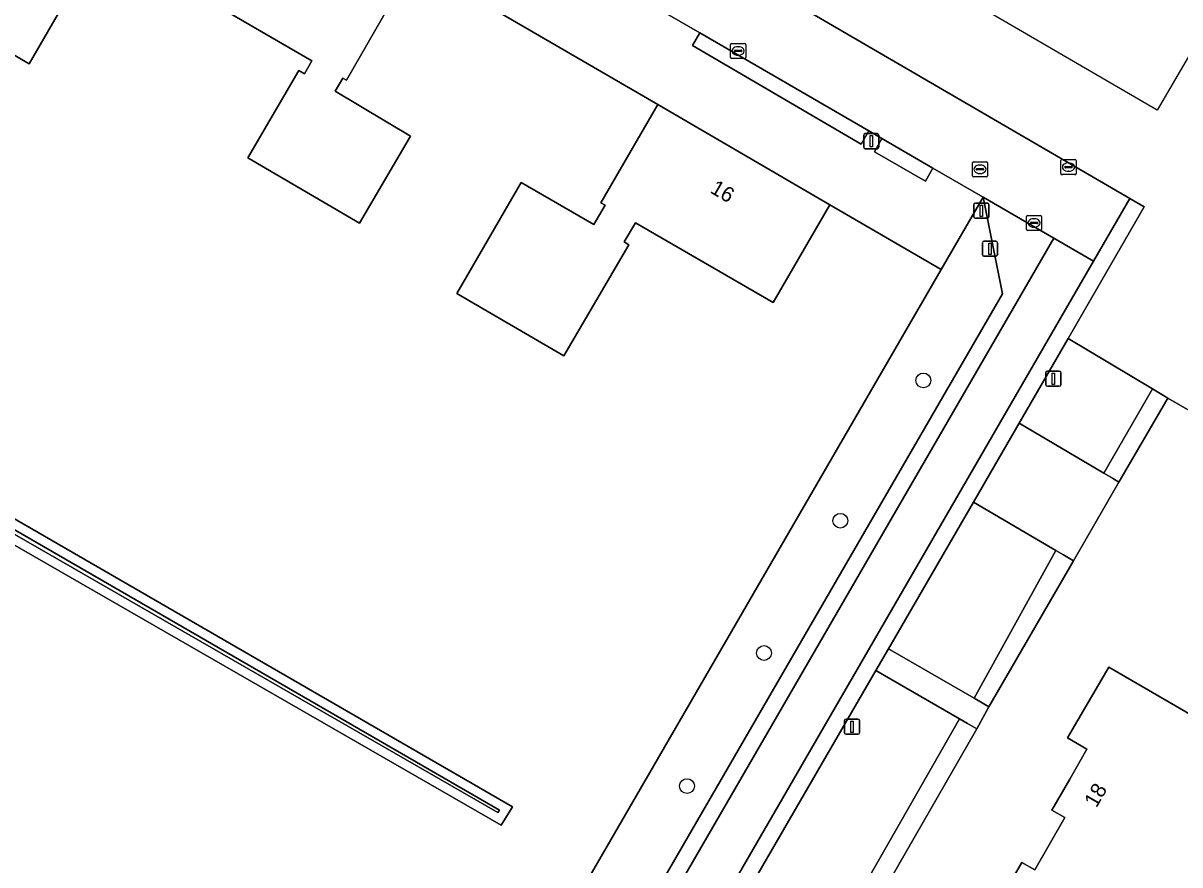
# Model space of a CAD drawing. Extents: x 156502 to 159075, y 384229 to 386100.
# Drawn here: x 157141.1 to 157217.5, y 385763.4 to 385818.9 of the extents above; entities that cross this region are included whole.
import ezdxf

# ---------------------------------------------------------------- set-up
doc = ezdxf.new("R2010")
doc.units = 0
for name, color, linetype in [('IMGEO_Afsluitpaal', 7, 'Continuous'), ('IMGEO_Berm_groen', 7, 'Continuous'), ('IMGEO_Boom', 7, 'Continuous'), ('IMGEO_Erf', 7, 'Continuous'), ('IMGEO_Grasland_overig', 7, 'Continuous'), ('IMGEO_Groenvoorziening', 7, 'Continuous'), ('IMGEO_Haag', 7, 'Continuous'), ('IMGEO_Hek', 7, 'Continuous'), ('IMGEO_Kolk', 7, 'Continuous'), ('IMGEO_Lichtmast', 7, 'Continuous'), ('IMGEO_Oever', 7, 'Continuous'), ('IMGEO_Pand', 7, 'Continuous'), ('IMGEO_Pand_nummerreeks', 7, 'Continuous'), ('IMGEO_Pand_vergunning_verleend', 7, 'Continuous'), ('IMGEO_Rijbaan_lokaal_gesloten', 7, 'Continuous'), ('IMGEO_Rijbaan_lokaal_halfverhard', 7, 'Continuous'), ('IMGEO_Rijbaan_lokaal_open', 7, 'Continuous'), ('IMGEO_Rioolput', 7, 'Continuous'), ('IMGEO_Voetpad_open', 7, 'Continuous'), ('IMGEO_Waterloop', 7, 'Continuous')]:
    doc.layers.add(name, color=color, linetype=linetype)

msp = doc.modelspace()

# ---------------------------------------------------------------- linework, layer by layer
at = {"layer": 'IMGEO_Afsluitpaal'}
for p, q in [((157203.9, 385806.17), (157203.9, 385806.97)), ((157203.9, 385806.97), (157203.9, 385806.17)), ((157204, 385807.07), (157204.79, 385807.07)), ((157204.79, 385807.07), (157204, 385807.07)), ((157204.89, 385806.97), (157204.89, 385806.17)), ((157204.89, 385806.17), (157204.89, 385806.97)), ((157204.79, 385806.07), (157204, 385806.07)), ((157204, 385806.07), (157204.79, 385806.07)), ((157204.466, 385803.659), (157204.466, 385804.459)), ((157204.466, 385804.459), (157204.466, 385803.659)), ((157204.566, 385804.559), (157205.356, 385804.559)), ((157205.356, 385804.559), (157204.566, 385804.559)), ((157205.456, 385804.459), (157205.456, 385803.659)), ((157205.456, 385803.659), (157205.456, 385804.459)), ((157205.356, 385803.559), (157204.566, 385803.559)), ((157204.566, 385803.559), (157205.356, 385803.559))]:
    msp.add_line(p, q, dxfattribs=at)
for points in [[(157204.32, 385806.945), (157204.47, 385806.945), (157204.47, 385806.195), (157204.32, 385806.195), (157204.32, 385806.945)], [(157204.886, 385804.434), (157205.036, 385804.434), (157205.036, 385803.684), (157204.886, 385803.684), (157204.886, 385804.434)]]:
    msp.add_lwpolyline(points, dxfattribs=at)
for centre, start, end in [((157204, 385806.97), 90, 180), ((157204, 385806.97), 90, 180), ((157204.79, 385806.97), 0, 90), ((157204.79, 385806.97), 360, 90), ((157204, 385806.17), 180, 270), ((157204, 385806.17), 180, 270), ((157204.79, 385806.17), 270, 0), ((157204.79, 385806.17), 270, 0), ((157204.566, 385804.459), 90, 180), ((157204.566, 385804.459), 90, 180), ((157205.356, 385804.459), 0, 90), ((157205.356, 385804.459), 360, 90), ((157204.566, 385803.659), 180, 270), ((157204.566, 385803.659), 180, 270), ((157205.356, 385803.659), 270, 0), ((157205.356, 385803.659), 270, 0)]:
    msp.add_arc(centre, 0.1, start, end, dxfattribs=at)
at = {"layer": 'IMGEO_Berm_groen'}
for points in [[(157205.798, 385801.093), (157204.517, 385807.457), (157201.732, 385802.693), (157157.489, 385726.3), (157149.855, 385730.69), (157148.433, 385728.196), (157156.009, 385723.887)], [(157162.191, 385725.838), (157205.798, 385801.093)]]:
    msp.add_lwpolyline(points, dxfattribs=at)
at = {"layer": 'IMGEO_Boom'}
for centre in [(157200.566, 385795.368), (157195.082, 385786.106), (157190.045, 385777.377), (157184.958, 385768.592)]:
    msp.add_circle(centre, 0.489, dxfattribs=at)
at = {"layer": 'IMGEO_Erf'}
for points in [[(157042.786, 385843.67), (157065.314, 385829.887), (157068.346, 385827.983), (157173.435, 385767.228), (157172.677, 385766.006), (157064.372, 385828.327), (157041.356, 385841.775)], [(157131.197, 385741.421), (157144.11, 385733.995), (157149.855, 385730.69), (157157.489, 385726.3), (157201.732, 385802.693), (157194.383, 385806.952), (157190.645, 385800.522), (157181.547, 385805.765), (157180.811, 385804.505), (157181.113, 385804.328), (157176.827, 385796.988), (157169.771, 385801.108), (157174.018, 385808.44), (157178.814, 385805.661), (157179.553, 385806.928), (157179.259, 385807.099), (157183.031, 385813.57), (157159.85, 385827.054)], [(157146.528, 385824.906), (157141.519, 385816.264), (157134.144, 385820.573)], [(157166.175, 385821.643), (157162.465, 385815.184), (157162.231, 385815.319), (157161.733, 385814.451), (157166.702, 385811.491), (157163.329, 385805.74), (157155.962, 385810.061), (157159.324, 385815.821), (157159.704, 385815.599), (157160.195, 385816.468), (157151.075, 385821.767)], [(157300.611, 385725.628), (157250.886, 385753.432), (157232.436, 385728.117), (157222.966, 385734.271), (157242.958, 385769.961), (157246.925, 385776.791), (157216.71, 385794.202), (157213.481, 385788.661), (157210.483, 385783.472), (157204.894, 385773.824), (157204.086, 385772.373), (157190.66, 385749.032), (157190.191, 385748.219), (157189.585, 385747.166), (157173.064, 385718.503), (157188.558, 385701.554)]]:
    msp.add_lwpolyline(points, dxfattribs=at)
msp.add_lwpolyline([(157216.825, 385762.498), (157214.836, 385759.028), (157215.782, 385758.513), (157212.125, 385752.188), (157207.442, 385754.89), (157208.164, 385756.155), (157204.143, 385758.489), (157207.06, 385763.557), (157207.934, 385763.062), (157209.905, 385766.51), (157209.04, 385767.011), (157210.228, 385769.058), (157211.364, 385771.036), (157210.092, 385771.773), (157212.805, 385776.435), (157227.391, 385767.994), (157224.692, 385763.333), (157223.414, 385764.038), (157221.09, 385760.054)], close=True, dxfattribs=at)
at = {"layer": 'IMGEO_Grasland_overig'}
msp.add_lwpolyline([(157186.511, 385823.495), (157214.196, 385807.371), (157215.153, 385806.818), (157210.12, 385798.131), (157215.692, 385794.809), (157216.71, 385794.202), (157246.925, 385776.791), (157272.043, 385820.045)], dxfattribs=at)
at = {"layer": 'IMGEO_Groenvoorziening'}
for points in [[(157196.965, 385811.84), (157185.809, 385818.305), (157185.313, 385817.465), (157196.454, 385810.969)], [(157197.832, 385811.333), (157197.341, 385810.462), (157200.709, 385808.513), (157201.192, 385809.384)], [(157215.606, 385794.649), (157215.692, 385794.809), (157210.12, 385798.131), (157206.888, 385792.553), (157212.477, 385789.254)], [(157216.71, 385794.202), (157215.692, 385794.809), (157215.606, 385794.649), (157212.477, 385789.254), (157213.054, 385788.913), (157213.481, 385788.661)], [(157209.322, 385784.15), (157203.866, 385787.336), (157198.256, 385777.654), (157203.918, 385774.387)], [(157210.483, 385783.472), (157209.828, 385783.854), (157209.322, 385784.15), (157203.918, 385774.387), (157204.337, 385774.145), (157204.894, 385773.824)], [(157202.954, 385773.026), (157197.423, 385776.216), (157183.392, 385751.998), (157189.099, 385748.819)], [(157204.086, 385772.373), (157203.479, 385772.723), (157202.954, 385773.026), (157189.099, 385748.819), (157189.61, 385748.533), (157190.191, 385748.219), (157190.66, 385749.032)]]:
    msp.add_lwpolyline(points, close=True, dxfattribs=at)
at = {"layer": 'IMGEO_Haag'}
for points in [[(157196.965, 385811.84), (157185.809, 385818.305), (157185.313, 385817.465), (157196.454, 385810.969)], [(157197.832, 385811.333), (157197.341, 385810.462), (157200.709, 385808.513), (157201.192, 385809.384)]]:
    msp.add_lwpolyline(points, close=True, dxfattribs=at)
at = {"layer": 'IMGEO_Hek'}
for points in [[(157183.031, 385813.57), (157159.85, 385827.054)], [(157201.732, 385802.693), (157194.383, 385806.952)], [(157149.855, 385730.69), (157157.489, 385726.3), (157201.732, 385802.693)]]:
    msp.add_lwpolyline(points, dxfattribs=at)
at = {"layer": 'IMGEO_Kolk'}
for p, q in [((157187.831, 385816.688), (157187.831, 385817.54)), ((157187.906, 385817.614), (157188.758, 385817.614)), ((157188.09, 385817.108), (157188.09, 385817.12)), ((157188.528, 385817.071), (157188.13, 385817.071)), ((157188.133, 385817.157), (157188.531, 385817.157)), ((157188.319, 385817.394), (157188.344, 385817.394)), ((157188.574, 385817.12), (157188.574, 385817.108)), ((157188.832, 385817.54), (157188.832, 385816.688)), ((157188.758, 385816.614), (157187.906, 385816.614)), ((157188.342, 385816.834), (157188.317, 385816.834)), ((157209.647, 385809.023), (157209.647, 385809.875)), ((157209.722, 385809.949), (157210.574, 385809.949)), ((157209.906, 385809.443), (157209.906, 385809.455)), ((157209.949, 385809.492), (157210.347, 385809.492)), ((157210.135, 385809.729), (157210.16, 385809.729)), ((157210.39, 385809.455), (157210.39, 385809.443)), ((157210.648, 385809.875), (157210.648, 385809.023)), ((157210.574, 385808.949), (157209.722, 385808.949)), ((157210.344, 385809.406), (157209.946, 385809.406)), ((157210.158, 385809.169), (157210.133, 385809.169)), ((157207.37, 385805.338), (157207.37, 385806.19)), ((157207.445, 385806.264), (157208.297, 385806.264)), ((157207.629, 385805.758), (157207.629, 385805.77)), ((157208.067, 385805.721), (157207.669, 385805.721)), ((157207.672, 385805.807), (157208.07, 385805.807)), ((157207.858, 385806.044), (157207.883, 385806.044)), ((157208.113, 385805.77), (157208.113, 385805.758)), ((157208.371, 385806.19), (157208.371, 385805.338)), ((157208.297, 385805.264), (157207.445, 385805.264)), ((157207.881, 385805.484), (157207.856, 385805.484))]:
    msp.add_line(p, q, dxfattribs=at)
for points in [[(157187.831, 385816.688), (157187.831, 385817.54)], [(157187.906, 385817.614), (157188.758, 385817.614)], [(157188.832, 385817.54), (157188.832, 385816.688)], [(157188.758, 385816.614), (157187.906, 385816.614)], [(157209.647, 385809.023), (157209.647, 385809.875)], [(157209.722, 385809.949), (157210.574, 385809.949)], [(157210.648, 385809.875), (157210.648, 385809.023)], [(157210.574, 385808.949), (157209.722, 385808.949)], [(157207.37, 385805.338), (157207.37, 385806.19)], [(157207.445, 385806.264), (157208.297, 385806.264)], [(157208.371, 385806.19), (157208.371, 385805.338)], [(157208.297, 385805.264), (157207.445, 385805.264)]]:
    msp.add_lwpolyline(points, dxfattribs=at)
for centre, radius, start, end in [((157187.908, 385817.538), 0.0765, 91.55205, 178.44795), ((157187.908, 385817.538), 0.0765, 91.55205, 178.44795), ((157188.13, 385817.117), 0.0403, 85.87752, 175.75265), ((157188.127, 385817.107), 0.0366, 178.93798, 274.71019), ((157188.531, 385817.114), 0.043, 264.86636, 352.45326), ((157188.535, 385817.119), 0.0386, 1.73085, 96.63898), ((157188.756, 385817.538), 0.0765, 1.55205, 88.44795), ((157188.756, 385817.538), 0.0765, 1.55205, 88.44795), ((157187.908, 385816.69), 0.0765, 181.55205, 268.44795), ((157187.908, 385816.69), 0.0765, 181.55205, 268.44795), ((157188.756, 385816.69), 0.0765, 271.55205, 358.44795), ((157188.756, 385816.69), 0.0765, 271.55205, 358.44795), ((157209.724, 385809.873), 0.0765, 91.55205, 178.44795), ((157209.724, 385809.873), 0.0765, 91.55205, 178.44795), ((157209.946, 385809.452), 0.0403, 85.87752, 175.75265), ((157209.943, 385809.442), 0.0366, 178.93798, 274.71019), ((157210.347, 385809.449), 0.043, 264.86636, 352.45326), ((157210.351, 385809.454), 0.0386, 1.73085, 96.63898), ((157210.572, 385809.873), 0.0765, 1.55205, 88.44795), ((157210.572, 385809.873), 0.0765, 1.55205, 88.44795), ((157209.724, 385809.025), 0.0765, 181.55205, 268.44795), ((157209.724, 385809.025), 0.0765, 181.55205, 268.44795), ((157210.572, 385809.025), 0.0765, 271.55205, 358.44795), ((157210.572, 385809.025), 0.0765, 271.55205, 358.44795), ((157207.447, 385806.188), 0.0765, 91.55205, 178.44795), ((157207.447, 385806.188), 0.0765, 91.55205, 178.44795), ((157207.669, 385805.767), 0.0403, 85.87752, 175.75265), ((157207.666, 385805.757), 0.0366, 178.93798, 274.71019), ((157208.07, 385805.764), 0.043, 264.86636, 352.45326), ((157208.074, 385805.769), 0.0386, 1.73085, 96.63898), ((157208.295, 385806.188), 0.0765, 1.55205, 88.44795), ((157208.295, 385806.188), 0.0765, 1.55205, 88.44795), ((157207.447, 385805.34), 0.0765, 181.55205, 268.44795), ((157207.447, 385805.34), 0.0765, 181.55205, 268.44795), ((157208.295, 385805.34), 0.0765, 271.55205, 358.44795), ((157208.295, 385805.34), 0.0765, 271.55205, 358.44795)]:
    msp.add_arc(centre, radius, start, end, dxfattribs=at)
for centre, major_axis, ratio, start_param, end_param in [((157188.318, 385817.114), (-0.387, 0.002), 0.722429, 4.712389, 7.853982), ((157188.343, 385817.114), (-0.39, 0.002), 0.717154, 1.570796, 4.712389), ((157210.134, 385809.449), (-0.387, 0.002), 0.722429, 4.712389, 7.853982), ((157210.159, 385809.449), (-0.39, 0.002), 0.717154, 1.570796, 4.712389), ((157207.857, 385805.764), (-0.387, 0.002), 0.722429, 4.712389, 7.853982), ((157207.882, 385805.764), (-0.39, 0.002), 0.717154, 1.570796, 4.712389)]:
    msp.add_ellipse(centre, major_axis=major_axis, ratio=ratio, start_param=start_param, end_param=end_param, dxfattribs=at)
at = {"layer": 'IMGEO_Lichtmast'}
for p, q in [((157196.628, 385810.761), (157196.628, 385811.561)), ((157196.628, 385811.561), (157196.628, 385810.761)), ((157196.728, 385811.661), (157197.518, 385811.661)), ((157197.518, 385811.661), (157196.728, 385811.661)), ((157197.618, 385811.561), (157197.618, 385810.761)), ((157197.618, 385810.761), (157197.618, 385811.561)), ((157197.518, 385810.661), (157196.728, 385810.661)), ((157196.728, 385810.661), (157197.518, 385810.661)), ((157208.652, 385795.082), (157208.652, 385795.882)), ((157208.652, 385795.882), (157208.652, 385795.082)), ((157208.752, 385795.982), (157209.542, 385795.982)), ((157209.542, 385795.982), (157208.752, 385795.982)), ((157209.642, 385795.882), (157209.642, 385795.082)), ((157209.642, 385795.082), (157209.642, 385795.882)), ((157209.542, 385794.982), (157208.752, 385794.982)), ((157208.752, 385794.982), (157209.542, 385794.982)), ((157195.357, 385772.112), (157195.357, 385772.912)), ((157195.357, 385772.912), (157195.357, 385772.112)), ((157195.457, 385773.012), (157196.247, 385773.012)), ((157196.247, 385773.012), (157195.457, 385773.012)), ((157196.347, 385772.912), (157196.347, 385772.112)), ((157196.347, 385772.112), (157196.347, 385772.912)), ((157196.247, 385772.012), (157195.457, 385772.012)), ((157195.457, 385772.012), (157196.247, 385772.012))]:
    msp.add_line(p, q, dxfattribs=at)
for points in [[(157197.048, 385811.536), (157197.198, 385811.536), (157197.198, 385810.786), (157197.048, 385810.786), (157197.048, 385811.536)], [(157209.072, 385795.857), (157209.222, 385795.857), (157209.222, 385795.107), (157209.072, 385795.107), (157209.072, 385795.857)], [(157195.777, 385772.887), (157195.927, 385772.887), (157195.927, 385772.137), (157195.777, 385772.137), (157195.777, 385772.887)]]:
    msp.add_lwpolyline(points, dxfattribs=at)
for centre, start, end in [((157196.728, 385811.561), 90, 180), ((157196.728, 385811.561), 90, 180), ((157197.518, 385811.561), 0, 90), ((157197.518, 385811.561), 360, 90), ((157196.728, 385810.761), 180, 270), ((157196.728, 385810.761), 180, 270), ((157197.518, 385810.761), 270, 0), ((157197.518, 385810.761), 270, 0), ((157208.752, 385795.882), 90, 180), ((157208.752, 385795.882), 90, 180), ((157209.542, 385795.882), 0, 90), ((157209.542, 385795.882), 360, 90), ((157208.752, 385795.082), 180, 270), ((157208.752, 385795.082), 180, 270), ((157209.542, 385795.082), 270, 0), ((157209.542, 385795.082), 270, 0), ((157195.457, 385772.912), 90, 180), ((157195.457, 385772.912), 90, 180), ((157196.247, 385772.912), 0, 90), ((157196.247, 385772.912), 360, 90), ((157195.457, 385772.112), 180, 270), ((157195.457, 385772.112), 180, 270), ((157196.247, 385772.112), 270, 0), ((157196.247, 385772.112), 270, 0)]:
    msp.add_arc(centre, 0.1, start, end, dxfattribs=at)
at = {"layer": 'IMGEO_Oever'}
for points in [[(157036.041, 385834.964), (157036.588, 385835.458), (157041.356, 385841.775), (157064.372, 385828.327), (157172.677, 385766.006), (157173.435, 385767.228), (157068.346, 385827.983), (157065.314, 385829.887), (157042.786, 385843.67), (157047.224, 385849.55), (157062.244, 385869.451), (157069.688, 385879.771), (157078.432, 385891.893), (157077.479, 385892.687), (157076.448, 385893.546)], [(157042.409, 385843.171), (157064.986, 385829.358), (157068.025, 385827.45), (157172.568, 385767.011), (157172.466, 385766.846), (157064.684, 385828.865), (157041.733, 385842.275)]]:
    msp.add_lwpolyline(points, dxfattribs=at)
at = {"layer": 'IMGEO_Pand'}
for points in [[(157134.715, 385841.68), (157130.951, 385835.263), (157140.002, 385829.967), (157139.464, 385829.042), (157139.17, 385829.213), (157134.144, 385820.573), (157141.519, 385816.264), (157146.528, 385824.906), (157141.44, 385827.871), (157141.989, 385828.812), (157142.29, 385828.637), (157146.045, 385835.121)], [(157155.595, 385829.52), (157151.075, 385821.767), (157160.195, 385816.468), (157159.704, 385815.599), (157159.324, 385815.821), (157155.962, 385810.061), (157163.329, 385805.74), (157166.702, 385811.491), (157161.733, 385814.451), (157162.231, 385815.319), (157162.465, 385815.184), (157166.175, 385821.643), (157159.093, 385825.747), (157159.85, 385827.054)], [(157194.383, 385806.952), (157183.031, 385813.57), (157179.259, 385807.099), (157179.553, 385806.928), (157178.814, 385805.661), (157174.018, 385808.44), (157169.771, 385801.108), (157176.827, 385796.988), (157181.113, 385804.328), (157180.811, 385804.505), (157181.547, 385805.765), (157190.645, 385800.522)], [(157227.391, 385767.994), (157212.805, 385776.435), (157210.092, 385771.773), (157211.364, 385771.036), (157210.228, 385769.058), (157209.04, 385767.011), (157209.905, 385766.51), (157207.934, 385763.062), (157207.06, 385763.557), (157204.143, 385758.489), (157208.164, 385756.155), (157207.442, 385754.89), (157212.125, 385752.188), (157215.782, 385758.513), (157214.836, 385759.028), (157216.825, 385762.498), (157221.09, 385760.054), (157223.414, 385764.038), (157224.692, 385763.333)]]:
    msp.add_lwpolyline(points, close=True, dxfattribs=at)
at = {"layer": 'IMGEO_Pand_vergunning_verleend'}
msp.add_lwpolyline([(157204.018, 385820.184), (157207.727, 385826.548), (157209.872, 385825.298), (157216.642, 385821.353), (157219.712, 385819.564), (157216.003, 385813.2)], close=True, dxfattribs=at)
at = {"layer": 'IMGEO_Rijbaan_lokaal_gesloten'}
msp.add_lwpolyline([(157164.84, 385722.131), (157211.808, 385803.246), (157209.184, 385804.754), (157163.025, 385725.068)], dxfattribs=at)
at = {"layer": 'IMGEO_Rijbaan_lokaal_halfverhard'}
msp.add_lwpolyline([(157163.025, 385725.068), (157209.184, 385804.754), (157204.517, 385807.457), (157205.798, 385801.093), (157162.191, 385725.838)], dxfattribs=at)
at = {"layer": 'IMGEO_Rijbaan_lokaal_open'}
for points in [[(157181.039, 385821.079), (157185.809, 385818.305), (157196.965, 385811.84), (157197.832, 385811.333), (157201.192, 385809.384), (157204.517, 385807.457), (157209.184, 385804.754), (157211.808, 385803.246), (157214.196, 385807.371), (157186.511, 385823.495)], [(157203.866, 385787.336), (157206.888, 385792.553), (157210.12, 385798.131), (157215.153, 385806.818), (157214.196, 385807.371), (157211.808, 385803.246), (157164.84, 385722.131)], [(157166.062, 385722.087), (157182.79, 385750.96), (157183.392, 385751.998), (157197.423, 385776.216), (157198.256, 385777.654), (157203.866, 385787.336)]]:
    msp.add_lwpolyline(points, dxfattribs=at)
msp.add_lwpolyline([(157213.481, 385788.661), (157213.054, 385788.913), (157212.477, 385789.254), (157206.888, 385792.553), (157203.866, 385787.336), (157209.322, 385784.15), (157209.828, 385783.854), (157210.483, 385783.472)], close=True, dxfattribs=at)
at = {"layer": 'IMGEO_Rioolput'}
for p, q in [((157203.802, 385808.879), (157203.802, 385809.731)), ((157203.877, 385809.805), (157204.729, 385809.805)), ((157204.29, 385809.585), (157204.315, 385809.585)), ((157204.803, 385809.731), (157204.803, 385808.879)), ((157204.729, 385808.805), (157203.877, 385808.805)), ((157204.061, 385809.299), (157204.061, 385809.311)), ((157204.499, 385809.262), (157204.101, 385809.262)), ((157204.104, 385809.348), (157204.502, 385809.348)), ((157204.313, 385809.025), (157204.288, 385809.025)), ((157204.545, 385809.311), (157204.545, 385809.299))]:
    msp.add_line(p, q, dxfattribs=at)
for points in [[(157203.802, 385808.879), (157203.802, 385809.731)], [(157203.877, 385809.805), (157204.729, 385809.805)], [(157204.803, 385809.731), (157204.803, 385808.879)], [(157204.729, 385808.805), (157203.877, 385808.805)]]:
    msp.add_lwpolyline(points, dxfattribs=at)
for centre, radius, start, end in [((157203.879, 385809.729), 0.0765, 91.55205, 178.44795), ((157203.879, 385809.729), 0.0765, 91.55205, 178.44795), ((157204.727, 385809.729), 0.0765, 1.55205, 88.44795), ((157204.727, 385809.729), 0.0765, 1.55205, 88.44795), ((157203.879, 385808.881), 0.0765, 181.55205, 268.44795), ((157203.879, 385808.881), 0.0765, 181.55205, 268.44795), ((157204.101, 385809.308), 0.0403, 85.87752, 175.75265), ((157204.098, 385809.298), 0.0366, 178.93798, 274.71019), ((157204.502, 385809.305), 0.043, 264.86636, 352.45326), ((157204.506, 385809.31), 0.0386, 1.73085, 96.63898), ((157204.727, 385808.881), 0.0765, 271.55205, 358.44795), ((157204.727, 385808.881), 0.0765, 271.55205, 358.44795)]:
    msp.add_arc(centre, radius, start, end, dxfattribs=at)
for centre, major_axis, ratio, start_param, end_param in [((157204.289, 385809.305), (-0.387, 0.002), 0.722429, 4.712389, 7.853982), ((157204.314, 385809.305), (-0.39, 0.002), 0.717154, 1.570796, 4.712389)]:
    msp.add_ellipse(centre, major_axis=major_axis, ratio=ratio, start_param=start_param, end_param=end_param, dxfattribs=at)
at = {"layer": 'IMGEO_Voetpad_open'}
msp.add_lwpolyline([(157159.85, 385827.054), (157183.031, 385813.57), (157194.383, 385806.952), (157201.732, 385802.693), (157204.517, 385807.457), (157201.192, 385809.384), (157200.709, 385808.513), (157197.341, 385810.462), (157197.832, 385811.333), (157196.965, 385811.84), (157196.454, 385810.969), (157185.313, 385817.465), (157185.809, 385818.305), (157181.039, 385821.079)], dxfattribs=at)
msp.add_lwpolyline([(157198.256, 385777.654), (157197.423, 385776.216), (157202.954, 385773.026), (157203.479, 385772.723), (157204.086, 385772.373), (157204.894, 385773.824), (157204.337, 385774.145), (157203.918, 385774.387)], close=True, dxfattribs=at)
at = {"layer": 'IMGEO_Waterloop'}
msp.add_lwpolyline([(157041.733, 385842.275), (157064.684, 385828.865), (157172.466, 385766.846), (157172.568, 385767.011), (157068.025, 385827.45), (157064.986, 385829.358), (157042.409, 385843.171)], dxfattribs=at)

# ---------------------------------------------------------------- texts
at = {"layer": 'IMGEO_Pand_nummerreeks'}
for s, rotation, p in [('16', 329.75851, (157186.422, 385807.796)), ('18', 60.13192, (157211.993, 385767.111))]:
    msp.add_text(s, height=1, rotation=rotation, dxfattribs=at).set_placement(p)

doc.saveas('drawing.dxf')
